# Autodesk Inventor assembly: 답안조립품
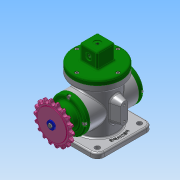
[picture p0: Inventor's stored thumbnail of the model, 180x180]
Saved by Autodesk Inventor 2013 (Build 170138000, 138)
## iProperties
Created: 2021-03
Part Number: 답안조립품
Document SubType Name: Assembly
Designer: Administrator
Author: Administrator
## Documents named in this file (19)
- C:\Users\Administrator\Desktop\710306v1004\답안조립품.iam
- C:\Users\Administrator\Desktop\710306v1004\본체.ipt
- C:\Users\Administrator\Desktop\710306v1004\E-링.ipt
- C:\Users\Administrator\Desktop\710306v1004\덮개.ipt
- C:\Users\Administrator\Desktop\710306v1004\뒤커버.ipt
- C:\Users\Administrator\Desktop\710306v1004\링크.ipt
- C:\Users\Administrator\Desktop\710306v1004\멈춤나사 M3.ipt
- C:\Users\Administrator\Desktop\710306v1004\베어링 17 x 40 x 12.ipt
- C:\Users\Administrator\Desktop\710306v1004\볼트 M4 x 10.ipt
- C:\Users\Administrator\Desktop\710306v1004\스프로킷.ipt
- C:\Users\Administrator\Desktop\710306v1004\슬라이더.ipt
- C:\Users\Administrator\Desktop\710306v1004\앞커버.ipt
- C:\Users\Administrator\Desktop\710306v1004\오일 실 17 30 8.ipt
- C:\Users\Administrator\Desktop\710306v1004\와셔 4x16.ipt
- C:\Users\Administrator\Desktop\710306v1004\클레비스 핀 6 x 22.ipt
- 클레비스 핀 6 x 22.ipt
- C:\Users\Administrator\Desktop\710306v1004\키 4 x 4 x 12.ipt
- C:\Users\Administrator\Desktop\710306v1004\편심축.ipt
- C:\Users\Administrator\Desktop\710306v1004\볼트 M4 x 8.ipt
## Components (1 placed, 1 different names)
1. E-링:2
